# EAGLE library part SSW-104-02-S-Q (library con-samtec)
THROUGH-HOLE .025" SQ POST SOCKET Source: Samtec SSW.pdf
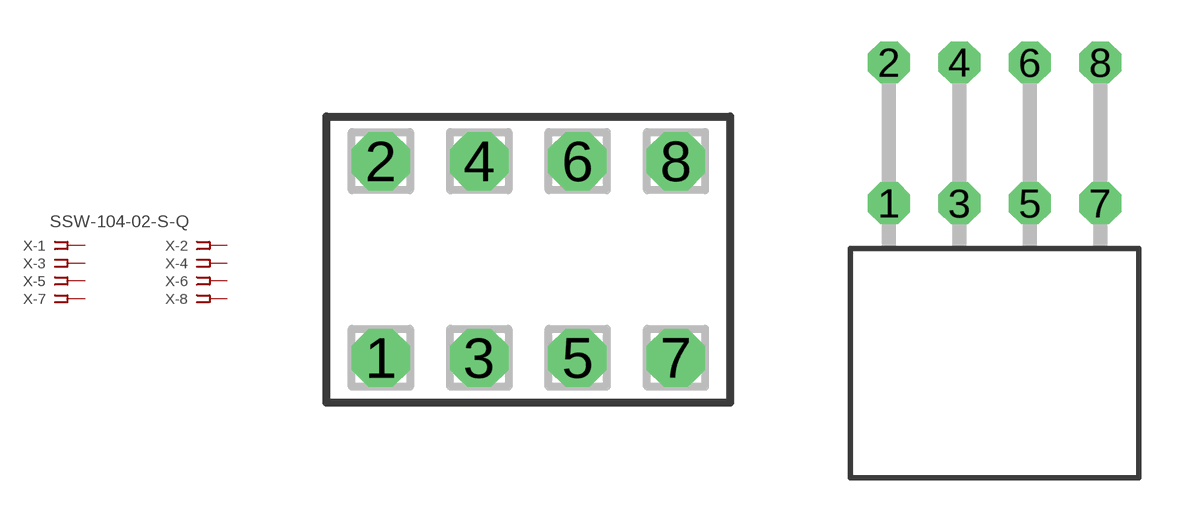
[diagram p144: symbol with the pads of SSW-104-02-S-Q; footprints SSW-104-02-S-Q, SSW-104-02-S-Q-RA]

Designator prefix X; gates -1=FPINV -2=FPIN -3=FPIN -4=FPIN -5=FPIN -6=FPIN -7=FPIN -8=FPIN

## SSW-104-02-S-Q (MPN: SSW-104-02-S-Q; OC_FARNELL: unknown; OC_NEWARK: 82P2475)  [SSW-104-02-S-Q]
1  -1:1  pas
2  -2:1  pas
3  -3:1  pas
4  -4:1  pas
5  -5:1  pas
6  -6:1  pas
7  -7:1  pas
8  -8:1  pas

## SSW-104-02-S-QRA (MPN: SSW-104-02-S-Q-RA; OC_FARNELL: unknown; OC_NEWARK: 82P2476)  [SSW-104-02-S-Q-RA]
Pads as for SSW-104-02-S-Q

## Footprint SSW-104-02-S-Q (pad centres in mm)
THROUGH-HOLE .025" SQ POST SOCKET Source: Samtec SSW.pdf
drill 1 pad 1.5 octagon: 1 -3.81,-2.54; 2 -3.81,2.54; 3 -1.27,-2.54; 4 -1.27,2.54; 5 1.27,-2.54; 6 1.27,2.54; 7 3.81,-2.54; 8 3.81,2.54

## Footprint SSW-104-02-S-Q-RA (pad centres in mm)
THROUGH-HOLE .025" SQ POST SOCKET Source: Samtec SSW.pdf
drill 1 pad 1.5 octagon: 1 -3.81,1.524; 2 -3.81,6.604; 3 -1.27,1.524; 4 -1.27,6.604; 5 1.27,1.524; 6 1.27,6.604; 7 3.81,1.524; 8 3.81,6.604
